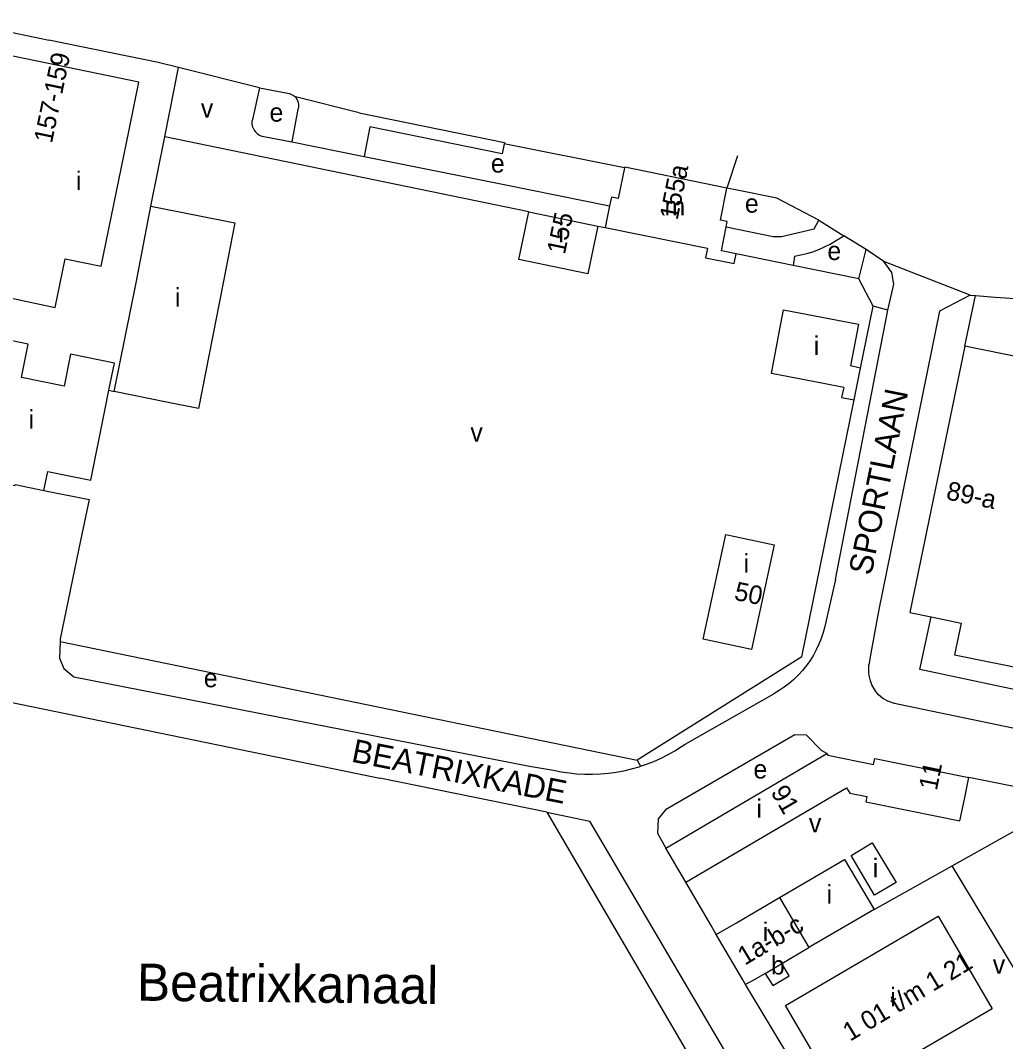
# Model space of a CAD drawing. Extents: x 157699 to 159683, y 381451 to 383293.
# Drawn here: x 158968.6 to 159180.6, y 382736.7 to 382956.5 of the extents above; entities that cross this region are included whole.
import ezdxf

# ---------------------------------------------------------------- set-up
doc = ezdxf.new("R2010")
doc.units = 0
for name, color, linetype in [('BLT_Basislijn', 7, 'Continuous'), ('BLT_Bebouwing', 7, 'Continuous'), ('BLT_Centroide', 7, 'Continuous'), ('BLT_Huisnummer', 7, 'Continuous'), ('BLT_Huisnummer_reeks', 7, 'Continuous'), ('BLT_Onderverdeling_panden', 7, 'Continuous'), ('BLT_Straatnaam', 7, 'Continuous'), ('BLT_Vlakafsluiter', 7, 'Continuous'), ('BLT_Waternaam_spoorwegen', 7, 'Continuous')]:
    doc.layers.add(name, color=color, linetype=linetype)

msp = doc.modelspace()

# ---------------------------------------------------------------- linework, layer by layer
at = {"layer": 'BLT_Basislijn'}
for p, q in [((159002.61, 382946.38), (158998.23, 382947.48)), ((158999.63, 382931.43), (159002.61, 382946.38)), ((159020.03, 382942.03), (159002.61, 382946.38)), ((158996.66, 382916.54), (158999.63, 382931.43)), ((159077.94, 382915.35), (158999.63, 382931.43)), ((159027.01, 382930.35), (159042.51, 382927.23)), ((159042.51, 382927.23), (159072.69, 382921.17)), ((159072.69, 382921.17), (159095.35, 382916.62)), ((159092.81, 382912.26), (159094.4, 382911.97)), ((159150.53, 382907.22), (159145.76, 382910.13)), ((159134.86, 382903.76), (159122.61, 382906.26)), ((159135.16, 382905.79), (159134.86, 382903.76)), ((159149.01, 382900.87), (159150.53, 382907.22)), ((159154.38, 382904.63), (159150.53, 382907.22)), ((159149.01, 382900.87), (159134.86, 382903.76)), ((159152.1, 382894.99), (159149.01, 382900.87)), ((159171.78, 382886.41), (159174.06, 382897.31)), ((159149.32, 382881.7), (159152.1, 382894.99)), ((158987.63, 382876.92), (158988.78, 382876.68)), ((159136.73, 382819.54), (159147.95, 382874.83)), ((159143.98, 382836.2), (159141.94, 382827.38)), ((159153.31, 382829.7), (159151.58, 382820.3)), ((158977.13, 382822.8), (159101.27, 382797.32)), ((159151.58, 382820.3), (159151.13, 382817.83)), ((159136.73, 382819.54), (159101.27, 382797.32)), ((158931.34, 382817), (159045.89, 382793.42)), ((159111.59, 382800.74), (159130.68, 382811.59)), ((159249.82, 382790.04), (159157.68, 382809.27)), ((159078.15, 382795.98), (159083.3, 382795.11)), ((159101.27, 382797.32), (159101.99, 382795.98)), ((159081.87, 382786.07), (159045.89, 382793.42)), ((159192.02, 382789.67), (159172.64, 382793.53)), ((159081.87, 382786.07), (159135.33, 382694.59)), ((159081.87, 382786.07), (159091.12, 382784.18)), ((159152.25, 382765.14), (159169.07, 382774.57)), ((159189.49, 382740.66), (159169.07, 382774.57)), ((159117.2, 382761.67), (159111.74, 382771.01)), ((159118.32, 382759.75), (159117.2, 382761.67)), ((159145.12, 382714.94), (159124.62, 382748.97))]:
    msp.add_line(p, q, dxfattribs=at)
for points in [[(158954.36, 382956.52), (158973.38, 382952.52), (158974.67, 382952.26)], [(158998.23, 382947.48), (158974.67, 382952.26)], [(159020.03, 382942.03), (159018.49, 382935.21)], [(159020.03, 382942.03), (159026.49, 382940.76), (159026.92, 382940.6), (159027.32, 382940.36), (159027.76, 382940.05)], [(159027.76, 382940.05), (159028.19, 382939.3), (159028.34, 382938.86), (159028.42, 382938.41), (159028.41, 382937.95), (159028.33, 382937.49), (159028.3, 382937.38), (159027.01, 382930.35)], [(159041.43, 382936.65), (159072.73, 382930.22), (159072.68, 382929.96)], [(159018.49, 382935.21), (159018.4, 382934.73), (159018.4, 382934.25), (159018.47, 382933.77), (159018.62, 382933.32), (159018.85, 382932.89), (159019.14, 382932.51), (159019.49, 382932.18), (159019.89, 382931.91), (159020.33, 382931.71), (159020.6, 382931.63), (159027.01, 382930.35)], [(159072.68, 382929.96), (159072.22, 382927.79), (159043.77, 382933.59), (159042.51, 382927.23)], [(159098.57, 382924.76), (159072.68, 382929.96)], [(159122.79, 382919.98), (159120.61, 382920.43)], [(159140.38, 382913.49), (159131.34, 382918.26), (159122.79, 382919.98)], [(159120.45, 382912.1), (159130.56, 382910.02), (159132.37, 382910.02), (159139.41, 382911.63), (159140.38, 382913.49)], [(159135.16, 382905.79), (159136.49, 382906.03), (159137.81, 382906.35), (159139.1, 382906.74), (159140.37, 382907.21), (159141.61, 382907.75), (159142.82, 382908.37), (159143.98, 382909.05), (159145.76, 382910.13)], [(159155.23, 382894.14), (159156.5, 382899.77), (159156.11, 382902.23), (159154.38, 382904.63)], [(159172.93, 382897.4), (159166.32, 382893.95), (159153.31, 382829.7)], [(159172.93, 382897.4), (159174.06, 382897.31)], [(159174.06, 382897.31), (159178.29, 382896.96), (159183.66, 382896.59), (159186.91, 382896.41)], [(159155.23, 382894.14), (159152.1, 382894.99)], [(159143.98, 382836.2), (159155.23, 382894.14)], [(158973.64, 382855.36), (158983.35, 382853.42), (158981.52, 382844.56), (158977.16, 382823.4), (158977.13, 382822.8)], [(159141.94, 382827.38), (159141.67, 382826.07), (159141.33, 382824.77), (159140.9, 382823.5), (159140.41, 382822.26), (159139.84, 382821.05), (159139.2, 382819.88), (159138.49, 382818.74), (159137.71, 382817.66), (159136.87, 382816.61), (159135.97, 382815.63), (159135.01, 382814.69), (159133.99, 382813.82), (159132.93, 382813.01), (159131.82, 382812.26), (159130.68, 382811.59)], [(159196.92, 382809.44), (159162.12, 382816.84), (159164.52, 382828.13)], [(158977.13, 382822.8), (158976.95, 382819.26), (158977.94, 382817.01), (158980.03, 382815.24), (159078.15, 382795.98)], [(159157.68, 382809.27), (159156.65, 382809.47), (159155.21, 382809.97), (159154.15, 382810.58), (159153.25, 382811.33), (159152.66, 382812.08), (159151.78, 382813.49), (159151.5, 382814.35), (159151.29, 382815.23), (159151.16, 382816.12), (159151.11, 382817.03), (159151.13, 382817.83)], [(159142.08, 382798.76), (159140.93, 382799.34), (159137.73, 382802.69), (159135.24, 382802.78), (159107.41, 382786.61), (159105.82, 382784.63), (159105.64, 382781.6), (159107.42, 382778.36)], [(159101.99, 382795.98), (159103.31, 382796.43), (159104.88, 382797.04), (159106.43, 382797.73), (159107.94, 382798.49), (159109.41, 382799.33), (159110.85, 382800.23), (159111.59, 382800.74)], [(159083.3, 382795.11), (159084.96, 382794.78), (159086.64, 382794.53), (159088.32, 382794.36), (159090.02, 382794.28), (159091.71, 382794.27), (159093.4, 382794.34), (159095.09, 382794.49), (159096.76, 382794.72), (159098.43, 382795.03), (159100.08, 382795.42), (159101.7, 382795.88), (159101.99, 382795.98)], [(159169.07, 382774.57), (159191.56, 382787.19), (159192.02, 382789.67)], [(159141.7, 382698.15), (159091.12, 382784.18)]]:
    msp.add_lwpolyline(points, dxfattribs=at)
at = {"layer": 'BLT_Bebouwing'}
for p, q in [((159095.35, 382916.62), (159094.4, 382911.97)), ((159077.94, 382915.35), (159092.81, 382912.26)), ((159184.15, 382883.86), (159171.78, 382886.41)), ((159149.32, 382881.7), (159147.2, 382882.16)), ((159147.95, 382874.83), (159149.32, 382881.7)), ((158986.73, 382872.53), (158987.63, 382876.92)), ((158973.64, 382855.36), (158974.47, 382859.43)), ((158974.47, 382859.43), (158979.08, 382858.49)), ((159171, 382826.79), (159169.6, 382819.99)), ((159169.6, 382819.99), (159197.9, 382814.15)), ((159107.42, 382778.36), (159142.08, 382798.76)), ((159111.74, 382771.01), (159107.42, 382778.36))]:
    msp.add_line(p, q, dxfattribs=at)
for points in [[(158994.08, 382943.25), (158954.01, 382951.45)], [(158952.34, 382943.32), (158943.81, 382901.6), (158976.07, 382894.73), (158978.21, 382905.21), (158985.97, 382903.62), (158991.98, 382932.99)], [(158991.98, 382932.99), (158994.08, 382943.25)], [(159098.57, 382924.76), (159097.23, 382918.17), (159095.73, 382918.47), (159095.35, 382916.62)], [(159098.61, 382924.92), (159098.57, 382924.76)], [(159120.61, 382920.43), (159098.61, 382924.92)], [(159120.45, 382912.1), (159120.68, 382913.24), (159119.21, 382913.54), (159120.61, 382920.43)], [(158996.66, 382916.54), (159014.73, 382912.92), (159012.18, 382900), (159006.86, 382873), (158999.99, 382874.35), (158988.78, 382876.68)], [(158988.78, 382876.68), (158993.45, 382900), (158996.66, 382916.54)], [(159092.81, 382912.26), (159091.83, 382907.5), (159090.69, 382901.98), (159075.82, 382905.05), (159076.94, 382910.51), (159077.94, 382915.35)], [(159122.61, 382906.26), (159119.4, 382906.91), (159120.45, 382912.1)], [(159094.4, 382911.97), (159116.43, 382907.48), (159116.02, 382905.45), (159122.19, 382904.19), (159122.61, 382906.26)], [(159145.75, 382877.54), (159141.38, 382878.38), (159130.17, 382880.53), (159131.86, 382889.33), (159132.81, 382894.24), (159148.93, 382891.14), (159147.2, 382882.16)], [(158977.95, 382877.81), (158968.79, 382879.68), (158970.26, 382886.82), (158959.1, 382889.1)], [(159171.78, 382886.41), (159159.95, 382829.07), (159164.52, 382828.13)], [(158987.63, 382876.92), (158988.82, 382882.71), (158979.35, 382884.65), (158977.95, 382877.81)], [(159145.75, 382877.54), (159145.26, 382875.33), (159147.95, 382874.83)], [(158979.08, 382858.49), (158983.69, 382857.56), (158986.73, 382872.53)], [(158959.21, 382858.38), (158959.15, 382858.05), (158967.39, 382856.38), (158967.44, 382856.62), (158973.64, 382855.36)], [(159164.52, 382828.13), (159171, 382826.79)], [(159142.08, 382798.76), (159142.31, 382798.36), (159152.17, 382796.37), (159152.43, 382797.65), (159172.64, 382793.53)], [(159159.72, 382786.44), (159170.74, 382784.2), (159171.7, 382788.88), (159172.64, 382793.53)], [(159111.74, 382771.01), (159146.36, 382791.34), (159147.04, 382790.22), (159150.73, 382789.47), (159150.5, 382788.32), (159159.72, 382786.44)], [(159131.89, 382767.71), (159145.9, 382775.93), (159152.25, 382765.14)], [(159118.32, 382759.75), (159122.63, 382762.28), (159131.89, 382767.71)], [(159152.25, 382765.14), (159138.26, 382756.94)], [(159133.21, 382744.52), (159166.08, 382763.7), (159177.71, 382743.78), (159144.85, 382724.61), (159133.21, 382744.52)], [(159124.62, 382748.97), (159124.02, 382750), (159118.32, 382759.75)], [(159132.4, 382753.52), (159138.26, 382756.94)], [(159128.82, 382751.37), (159129.71, 382750), (159130.49, 382748.79), (159132.57, 382750), (159134.03, 382750.85), (159132.4, 382753.52)], [(159128.82, 382751.37), (159126.43, 382750), (159124.62, 382748.97)]]:
    msp.add_lwpolyline(points, dxfattribs=at)
for points in [[(159115.49, 382823.34), (159120.38, 382845.86), (159130.76, 382843.61), (159125.87, 382821.09)], [(159147.32, 382776.74), (159151.82, 382779.48), (159157.01, 382770.96), (159152.33, 382768.21)]]:
    msp.add_lwpolyline(points, close=True, dxfattribs=at)
at = {"layer": 'BLT_Onderverdeling_panden'}
for p, q in [((159131.89, 382767.71), (159138.26, 382756.94)), ((159128.82, 382751.37), (159132.4, 382753.52))]:
    msp.add_line(p, q, dxfattribs=at)
at = {"layer": 'BLT_Vlakafsluiter'}
for p, q in [((159041.43, 382936.65), (159027.76, 382940.05)), ((159122.9, 382927.36), (159120.61, 382920.43)), ((159140.38, 382913.49), (159145.76, 382910.13)), ((159172.93, 382897.4), (159154.38, 382904.63))]:
    msp.add_line(p, q, dxfattribs=at)

# ---------------------------------------------------------------- texts
at = {"layer": 'BLT_Centroide'}
for s, p in [('v', (159007.4, 382935.6)), ('e', (159022.17, 382934.73)), ('e', (159069.81, 382923.77)), ('i', (158980.52, 382920)), ('m', (159107.16, 382914.56)), ('e', (159124.47, 382915.14)), ('i', (159084.33, 382908.72)), ('e', (159142.22, 382904.94)), ('i', (159001.81, 382894.94)), ('i', (159139.3, 382884.53)), ('i', (158970.33, 382868.66)), ('v', (159065.4, 382865.87)), ('i', (159124.2, 382837.68)), ('e', (159008.03, 382812.98)), ('e', (159126.31, 382793.35)), ('i', (159126.94, 382784.88)), ('v', (159138.24, 382781.74)), ('i', (159151.99, 382772.09)), ('i', (159142.06, 382766.44)), ('i', (159128.29, 382758.34)), ('b', (159130.07, 382751.16)), ('v', (159177.81, 382751.33)), ('i', (159155.74, 382744.31))]:
    msp.add_text(s, height=4, dxfattribs=at).set_placement(p)
at = {"layer": 'BLT_Huisnummer'}
for s, rotation, p in [('155a', 78.4841, (159109.97, 382913.4)), ('155', 78.367, (159085.73, 382906)), ('50', 348.367, (159121.98, 382831.84))]:
    msp.add_text(s, height=4, rotation=rotation, dxfattribs=at).set_placement(p)
at = {"layer": 'BLT_Huisnummer_reeks'}
for s, rotation, p in [('157-159', 78.2618, (158975.34, 382929.92)), ('89-a', 348.342, (159167.59, 382853.47)), ('11', 78.4714, (159165.75, 382790.6)), ('91', 300.4141, (159129.92, 382790.43)), ('1a-b-c', 30.9332, (159124.45, 382753.03)), ('1 01 t/m 1 21', 31.0646, (159147.09, 382736.66))]:
    msp.add_text(s, height=4, rotation=rotation, dxfattribs=at).set_placement(p)
at = {"layer": 'BLT_Straatnaam'}
for s, rotation, p in [('SPORTLAAN', 78.6766, (159151.68, 382836.9)), ('BEATRIXKADE', 348.7511, (159039.59, 382797))]:
    msp.add_text(s, height=5, rotation=rotation, dxfattribs=at).set_placement(p)
at = {"layer": 'BLT_Waternaam_spoorwegen'}
msp.add_text('Beatrixkanaal', height=8, rotation=359.3753, dxfattribs=at).set_placement((158993.61, 382745.52))

doc.saveas('drawing.dxf')
